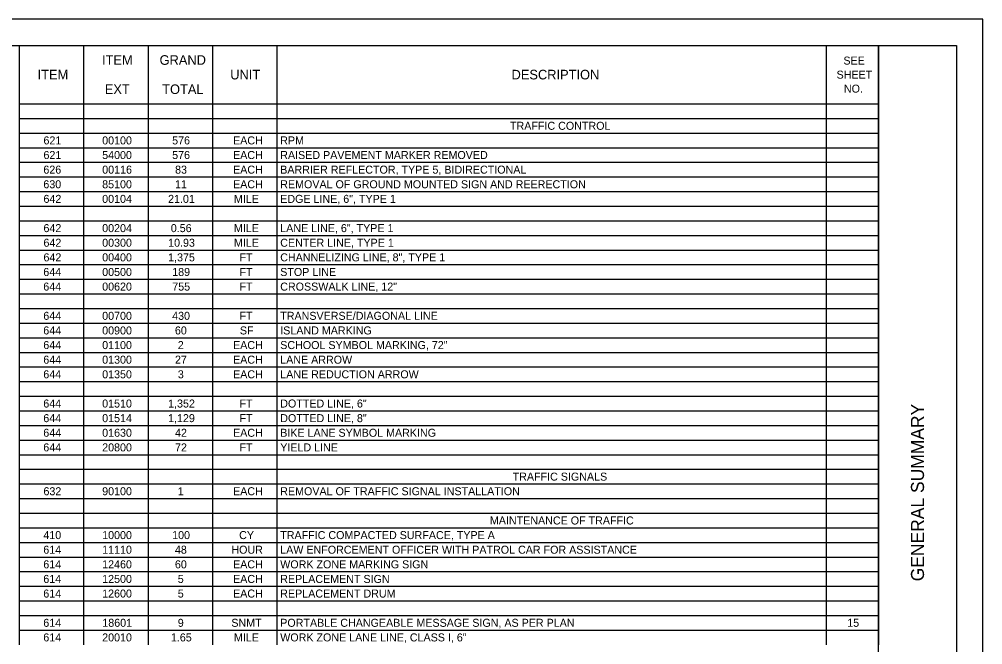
# Model space of a CAD drawing. Extents: x 0 to 34, y 0 to 22.
# Drawn here: x 15.54 to 34, y 10.02 to 22 of the extents above; entities that cross this region are included whole.
import ezdxf

# ---------------------------------------------------------------- set-up
doc = ezdxf.new("R2010")
doc.units = 0
for name, color, linetype in [('SH_Border', 7, 'Continuous'), ('SH_Cut_Line', 7, 'Continuous'), ('SH_Data', 7, 'Continuous'), ('SH_Text', 7, 'Continuous')]:
    doc.layers.add(name, color=color, linetype=linetype)

msp = doc.modelspace()

# ---------------------------------------------------------------- linework, layer by layer
at = {"layer": 'SH_Border'}
msp.add_line((32, 0.5), (32, 21.5), dxfattribs=at)
msp.add_lwpolyline([(1.5, 21.5), (33.5, 21.5), (33.5, 0.5), (1.5, 0.5)], close=True, dxfattribs=at)
at = {"layer": 'SH_Cut_Line'}
msp.add_lwpolyline([(0, 0), (34, 0), (34, 22), (0, 22)], close=True, dxfattribs=at)
at = {"layer": 'SH_Text'}
for p, q in [((15.537, 21.5), (18.005, 21.5)), ((15.537, 21.5), (15.537, 21.22)), ((16.771, 21.5), (16.771, 21.22)), ((18.005, 21.5), (19.239, 21.5)), ((18.005, 21.5), (18.005, 21.22)), ((19.239, 21.5), (32.004, 21.5)), ((19.239, 21.5), (19.239, 21.22)), ((20.473, 21.5), (20.473, 21.22)), ((31.001, 21.5), (31.001, 21.22)), ((32.004, 21.5), (32.004, 21.22)), ((15.537, 21.22), (15.537, 20.94)), ((16.771, 21.22), (16.771, 20.94)), ((18.005, 21.22), (18.005, 20.94)), ((19.239, 21.22), (19.239, 20.94)), ((20.473, 21.22), (20.473, 20.94)), ((31.001, 21.22), (31.001, 20.94)), ((32.004, 21.22), (32.004, 20.94)), ((15.537, 20.94), (15.537, 20.66)), ((16.771, 20.94), (16.771, 20.66)), ((18.005, 20.94), (18.005, 20.66)), ((19.239, 20.94), (19.239, 20.66)), ((20.473, 20.94), (20.473, 20.66)), ((31.001, 20.94), (31.001, 20.66)), ((32.004, 20.94), (32.004, 20.66)), ((15.537, 20.66), (15.537, 20.38)), ((16.771, 20.66), (16.771, 20.38)), ((18.005, 20.66), (18.005, 20.38)), ((19.239, 20.66), (19.239, 20.38)), ((20.473, 20.66), (20.473, 20.38)), ((31.001, 20.66), (31.001, 20.38)), ((32.004, 20.66), (32.004, 20.38)), ((15.537, 20.38), (18.005, 20.38)), ((15.537, 20.38), (15.537, 20.1)), ((16.771, 20.38), (16.771, 20.1)), ((18.005, 20.38), (19.239, 20.38)), ((18.005, 20.38), (18.005, 20.1)), ((19.239, 20.38), (32.004, 20.38)), ((19.239, 20.38), (19.239, 20.1)), ((20.473, 20.38), (20.473, 20.1)), ((31.001, 20.38), (31.001, 20.1)), ((32.004, 20.38), (32.004, 20.1)), ((15.537, 20.1), (18.005, 20.1)), ((15.537, 20.1), (15.537, 18.7)), ((16.771, 20.1), (16.771, 18.7)), ((18.005, 20.1), (19.239, 20.1)), ((18.005, 20.1), (18.005, 18.7)), ((19.239, 20.1), (32.004, 20.1)), ((19.239, 20.1), (19.239, 18.7)), ((20.473, 20.1), (20.473, 18.7)), ((31.001, 20.1), (31.001, 18.7)), ((32.004, 20.1), (32.004, 18.7)), ((15.537, 19.82), (18.005, 19.82)), ((18.005, 19.82), (19.239, 19.82)), ((19.239, 19.82), (32.004, 19.82)), ((15.537, 19.54), (18.005, 19.54)), ((18.005, 19.54), (19.239, 19.54)), ((19.239, 19.54), (32.004, 19.54)), ((15.537, 19.26), (18.005, 19.26)), ((18.005, 19.26), (19.239, 19.26)), ((19.239, 19.26), (32.004, 19.26)), ((15.537, 18.98), (18.005, 18.98)), ((18.005, 18.98), (19.239, 18.98)), ((19.239, 18.98), (32.004, 18.98)), ((15.537, 18.7), (18.005, 18.7)), ((15.537, 18.7), (15.537, 18.14)), ((16.771, 18.7), (16.771, 18.14)), ((18.005, 18.7), (19.239, 18.7)), ((18.005, 18.7), (18.005, 18.14)), ((19.239, 18.7), (32.004, 18.7)), ((19.239, 18.7), (19.239, 18.14)), ((20.473, 18.7), (20.473, 18.14)), ((31.001, 18.7), (31.001, 18.14)), ((32.004, 18.7), (32.004, 18.14)), ((15.537, 18.42), (18.005, 18.42)), ((18.005, 18.42), (19.239, 18.42)), ((19.239, 18.42), (32.004, 18.42)), ((15.537, 18.14), (18.005, 18.14)), ((15.537, 18.14), (15.537, 17.86)), ((16.771, 18.14), (16.771, 17.86)), ((18.005, 18.14), (19.239, 18.14)), ((18.005, 18.14), (18.005, 17.86)), ((19.239, 18.14), (32.004, 18.14)), ((19.239, 18.14), (19.239, 17.86)), ((20.473, 18.14), (20.473, 17.86)), ((31.001, 18.14), (31.001, 17.86)), ((32.004, 18.14), (32.004, 17.86)), ((15.537, 17.86), (18.005, 17.86)), ((15.537, 17.86), (15.537, 17.58)), ((16.771, 17.86), (16.771, 17.58)), ((18.005, 17.86), (19.239, 17.86)), ((18.005, 17.86), (18.005, 17.58)), ((19.239, 17.86), (32.004, 17.86)), ((19.239, 17.86), (19.239, 17.58)), ((20.473, 17.86), (20.473, 17.58)), ((31.001, 17.86), (31.001, 17.58)), ((32.004, 17.86), (32.004, 17.58)), ((15.537, 17.58), (18.005, 17.58)), ((15.537, 17.58), (15.537, 17.3)), ((16.771, 17.58), (16.771, 17.3)), ((18.005, 17.58), (19.239, 17.58)), ((18.005, 17.58), (18.005, 17.3)), ((19.239, 17.58), (32.004, 17.58)), ((19.239, 17.58), (19.239, 17.3)), ((20.473, 17.58), (20.473, 17.3)), ((31.001, 17.58), (31.001, 17.3)), ((32.004, 17.58), (32.004, 17.3)), ((15.537, 17.3), (18.005, 17.3)), ((15.537, 17.3), (15.537, 17.02)), ((16.771, 17.3), (16.771, 17.02)), ((18.005, 17.3), (19.239, 17.3)), ((18.005, 17.3), (18.005, 17.02)), ((19.239, 17.3), (32.004, 17.3)), ((19.239, 17.3), (19.239, 17.02)), ((20.473, 17.3), (20.473, 17.02)), ((31.001, 17.3), (31.001, 17.02)), ((32.004, 17.3), (32.004, 17.02)), ((15.537, 17.02), (18.005, 17.02)), ((15.537, 17.02), (15.537, 16.74)), ((16.771, 17.02), (16.771, 16.74)), ((18.005, 17.02), (19.239, 17.02)), ((18.005, 17.02), (18.005, 16.74)), ((19.239, 17.02), (32.004, 17.02)), ((19.239, 17.02), (19.239, 16.74)), ((20.473, 17.02), (20.473, 16.74)), ((31.001, 17.02), (31.001, 16.74)), ((32.004, 17.02), (32.004, 16.74)), ((15.537, 16.74), (18.005, 16.74)), ((15.537, 16.74), (15.537, 16.18)), ((16.771, 16.74), (16.771, 16.18)), ((18.005, 16.74), (19.239, 16.74)), ((18.005, 16.74), (18.005, 16.18)), ((19.239, 16.74), (32.004, 16.74)), ((19.239, 16.74), (19.239, 16.18)), ((20.473, 16.74), (20.473, 16.18)), ((31.001, 16.74), (31.001, 16.18)), ((32.004, 16.74), (32.004, 16.18)), ((15.537, 16.46), (18.005, 16.46)), ((18.005, 16.46), (19.239, 16.46)), ((19.239, 16.46), (32.004, 16.46)), ((15.537, 16.18), (18.005, 16.18)), ((15.537, 16.18), (15.537, 15.9)), ((16.771, 16.18), (16.771, 15.9)), ((18.005, 16.18), (19.239, 16.18)), ((18.005, 16.18), (18.005, 15.9)), ((19.239, 16.18), (32.004, 16.18)), ((19.239, 16.18), (19.239, 15.9)), ((20.473, 16.18), (20.473, 15.9)), ((31.001, 16.18), (31.001, 15.9)), ((32.004, 16.18), (32.004, 15.9)), ((15.537, 15.9), (18.005, 15.9)), ((15.537, 15.9), (15.537, 15.62)), ((16.771, 15.9), (16.771, 15.62)), ((18.005, 15.9), (19.239, 15.9)), ((18.005, 15.9), (18.005, 15.62)), ((19.239, 15.9), (32.004, 15.9)), ((19.239, 15.9), (19.239, 15.62)), ((20.473, 15.9), (20.473, 15.62)), ((31.001, 15.9), (31.001, 15.62)), ((32.004, 15.9), (32.004, 15.62)), ((15.537, 15.62), (18.005, 15.62)), ((15.537, 15.62), (15.537, 15.34)), ((16.771, 15.62), (16.771, 15.34)), ((18.005, 15.62), (19.239, 15.62)), ((18.005, 15.62), (18.005, 15.34)), ((19.239, 15.62), (32.004, 15.62)), ((19.239, 15.62), (19.239, 15.34)), ((20.473, 15.62), (20.473, 15.34)), ((31.001, 15.62), (31.001, 15.34)), ((32.004, 15.62), (32.004, 15.34)), ((15.537, 15.34), (18.005, 15.34)), ((15.537, 15.34), (15.537, 14.78)), ((16.771, 15.34), (16.771, 14.78)), ((18.005, 15.34), (19.239, 15.34)), ((18.005, 15.34), (18.005, 14.78)), ((19.239, 15.34), (32.004, 15.34)), ((19.239, 15.34), (19.239, 14.78)), ((20.473, 15.34), (20.473, 14.78)), ((31.001, 15.34), (31.001, 14.78)), ((32.004, 15.34), (32.004, 14.78)), ((15.537, 15.06), (18.005, 15.06)), ((18.005, 15.06), (19.239, 15.06)), ((19.239, 15.06), (32.004, 15.06)), ((15.537, 14.78), (18.005, 14.78)), ((15.537, 14.78), (15.537, 14.5)), ((16.771, 14.78), (16.771, 14.5)), ((18.005, 14.78), (19.239, 14.78)), ((18.005, 14.78), (18.005, 14.5)), ((19.239, 14.78), (32.004, 14.78)), ((19.239, 14.78), (19.239, 14.5)), ((20.473, 14.78), (20.473, 14.5)), ((31.001, 14.78), (31.001, 14.5)), ((32.004, 14.78), (32.004, 14.5)), ((15.537, 14.5), (18.005, 14.5)), ((15.537, 14.5), (15.537, 14.22)), ((16.771, 14.5), (16.771, 14.22)), ((18.005, 14.5), (19.239, 14.5)), ((18.005, 14.5), (18.005, 14.22)), ((19.239, 14.5), (32.004, 14.5)), ((19.239, 14.5), (19.239, 14.22)), ((20.473, 14.5), (20.473, 14.22)), ((31.001, 14.5), (31.001, 14.22)), ((32.004, 14.5), (32.004, 14.22)), ((15.537, 14.22), (18.005, 14.22)), ((15.537, 14.22), (15.537, 13.94)), ((16.771, 14.22), (16.771, 13.94)), ((18.005, 14.22), (19.239, 14.22)), ((18.005, 14.22), (18.005, 13.94)), ((19.239, 14.22), (32.004, 14.22)), ((19.239, 14.22), (19.239, 13.94)), ((20.473, 14.22), (20.473, 13.94)), ((31.001, 14.22), (31.001, 13.94)), ((32.004, 14.22), (32.004, 13.94)), ((15.537, 13.94), (18.005, 13.94)), ((15.537, 13.94), (15.537, 11.7)), ((16.771, 13.94), (16.771, 11.7)), ((18.005, 13.94), (19.239, 13.94)), ((18.005, 13.94), (18.005, 11.7)), ((19.239, 13.94), (32.004, 13.94)), ((19.239, 13.94), (19.239, 11.7)), ((20.473, 13.94), (20.473, 11.7)), ((31.001, 13.94), (31.001, 11.7)), ((32.004, 13.94), (32.004, 11.7)), ((15.537, 13.66), (18.005, 13.66)), ((18.005, 13.66), (19.239, 13.66)), ((19.239, 13.66), (32.004, 13.66)), ((15.537, 13.38), (18.005, 13.38)), ((18.005, 13.38), (19.239, 13.38)), ((19.239, 13.38), (32.004, 13.38)), ((15.537, 13.1), (18.005, 13.1)), ((18.005, 13.1), (19.239, 13.1)), ((19.239, 13.1), (32.004, 13.1)), ((15.537, 12.82), (18.005, 12.82)), ((18.005, 12.82), (19.239, 12.82)), ((19.239, 12.82), (32.004, 12.82)), ((15.537, 12.54), (18.005, 12.54)), ((18.005, 12.54), (19.239, 12.54)), ((19.239, 12.54), (32.004, 12.54)), ((15.537, 12.26), (18.005, 12.26)), ((18.005, 12.26), (19.239, 12.26)), ((19.239, 12.26), (32.004, 12.26)), ((15.537, 11.98), (18.005, 11.98)), ((18.005, 11.98), (19.239, 11.98)), ((19.239, 11.98), (32.004, 11.98)), ((15.537, 11.7), (18.005, 11.7)), ((15.537, 11.7), (15.537, 11.42)), ((16.771, 11.7), (16.771, 11.42)), ((18.005, 11.7), (19.239, 11.7)), ((18.005, 11.7), (18.005, 11.42)), ((19.239, 11.7), (32.004, 11.7)), ((19.239, 11.7), (19.239, 11.42)), ((20.473, 11.7), (20.473, 11.42)), ((31.001, 11.7), (31.001, 11.42)), ((32.004, 11.7), (32.004, 11.42)), ((15.537, 11.42), (18.005, 11.42)), ((15.537, 11.42), (15.537, 10.3)), ((16.771, 11.42), (16.771, 10.3)), ((18.005, 11.42), (19.239, 11.42)), ((18.005, 11.42), (18.005, 10.3)), ((19.239, 11.42), (32.004, 11.42)), ((19.239, 11.42), (19.239, 10.3)), ((20.473, 11.42), (20.473, 10.3)), ((31.001, 11.42), (31.001, 10.3)), ((32.004, 11.42), (32.004, 10.3)), ((15.537, 11.14), (18.005, 11.14)), ((18.005, 11.14), (19.239, 11.14)), ((19.239, 11.14), (32.004, 11.14)), ((15.537, 10.86), (18.005, 10.86)), ((18.005, 10.86), (19.239, 10.86)), ((19.239, 10.86), (32.004, 10.86)), ((15.537, 10.58), (18.005, 10.58)), ((18.005, 10.58), (19.239, 10.58)), ((19.239, 10.58), (32.004, 10.58)), ((15.537, 10.3), (18.005, 10.3)), ((15.537, 10.3), (15.537, 10.02)), ((16.771, 10.3), (16.771, 10.02)), ((18.005, 10.3), (19.239, 10.3)), ((18.005, 10.3), (18.005, 10.02)), ((19.239, 10.3), (32.004, 10.3)), ((19.239, 10.3), (19.239, 10.02)), ((20.473, 10.3), (20.473, 10.02)), ((31.001, 10.3), (31.001, 10.02)), ((32.004, 10.3), (32.004, 10.02))]:
    msp.add_line(p, q, dxfattribs=at)

# ---------------------------------------------------------------- texts
at = {"layer": 'SH_Data'}
msp.add_text('GENERAL SUMMARY', height=0.25, rotation=90, dxfattribs=at).set_placement((32.875, 11.235))
at = {"layer": 'SH_Text'}
for s, height, p in [('ITEM', 0.184, (17.123, 21.128)), ('GRAND', 0.184, (18.226, 21.128)), ('SEE ', 0.1533, (31.33, 21.132)), ('ITEM', 0.184, (15.889, 20.848)), ('UNIT', 0.184, (19.58, 20.848)), ('DESCRIPTION', 0.184, (24.971, 20.848)), ('SHEET ', 0.1533, (31.199, 20.863)), ('EXT', 0.184, (17.176, 20.568)), ('TOTAL', 0.184, (18.276, 20.568)), ('NO.', 0.1533, (31.34, 20.595)), ('TRAFFIC CONTROL', 0.15334, (24.941, 19.883)), ('621', 0.1533, (16.001, 19.603)), ('00100', 0.1533, (17.126, 19.603)), ('576', 0.1533, (18.467, 19.603)), ('EACH', 0.1533, (19.634, 19.603)), ('RPM', 0.1533, (20.538, 19.603)), ('621', 0.1533, (16.001, 19.323)), ('54000', 0.1533, (17.126, 19.323)), ('576', 0.1533, (18.467, 19.323)), ('EACH', 0.1533, (19.634, 19.323)), ('RAISED PAVEMENT MARKER REMOVED', 0.15334, (20.538, 19.323)), ('626', 0.1533, (15.999, 19.043)), ('00116', 0.1533, (17.127, 19.043)), ('83', 0.1533, (18.523, 19.043)), ('EACH', 0.1533, (19.634, 19.043)), ('BARRIER REFLECTOR, TYPE 5, BIDIRECTIONAL', 0.15334, (20.538, 19.043)), ('630', 0.1533, (15.999, 18.763)), ('85100', 0.1533, (17.126, 18.763)), ('11', 0.1533, (18.522, 18.763)), ('EACH', 0.1533, (19.634, 18.763)), ('REMOVAL OF GROUND MOUNTED SIGN AND REERECTION', 0.15334, (20.538, 18.763)), ('642', 0.1533, (16.001, 18.483)), ('00104', 0.1533, (17.126, 18.483)), ('21.01', 0.1533, (18.389, 18.483)), ('MILE', 0.1533, (19.651, 18.483)), ('EDGE LINE, 6", TYPE 1', 0.15334, (20.538, 18.483)), ('642', 0.1533, (16.001, 17.923)), ('00204', 0.1533, (17.126, 17.923)), ('0.56', 0.1533, (18.441, 17.923)), ('MILE', 0.1533, (19.651, 17.923)), ('LANE LINE, 6", TYPE 1', 0.15334, (20.538, 17.923)), ('642', 0.1533, (16.001, 17.643)), ('00300', 0.1533, (17.126, 17.643)), ('10.93', 0.1533, (18.39, 17.643)), ('MILE', 0.1533, (19.651, 17.643)), ('CENTER LINE, TYPE 1', 0.15334, (20.538, 17.643)), ('642', 0.1533, (16.001, 17.363)), ('00400', 0.1533, (17.126, 17.363)), ('1,375', 0.1533, (18.39, 17.363)), ('FT', 0.1533, (19.758, 17.363)), ('CHANNELIZING LINE, 8", TYPE 1', 0.15334, (20.538, 17.363)), ('644', 0.1533, (15.998, 17.083)), ('00500', 0.1533, (17.126, 17.083)), ('189', 0.1533, (18.468, 17.083)), ('FT', 0.1533, (19.758, 17.083)), ('STOP LINE', 0.1533, (20.538, 17.083)), ('644', 0.1533, (15.998, 16.803)), ('00620', 0.1533, (17.126, 16.803)), ('755', 0.1533, (18.469, 16.803)), ('FT', 0.1533, (19.758, 16.803)), ('CROSSWALK LINE, 12"', 0.15334, (20.538, 16.803)), ('644', 0.1533, (15.998, 16.243)), ('00700', 0.1533, (17.126, 16.243)), ('430', 0.1533, (18.467, 16.243)), ('FT', 0.1533, (19.758, 16.243)), ('TRANSVERSE/DIAGONAL LINE', 0.15334, (20.538, 16.243)), ('644', 0.1533, (15.998, 15.963)), ('00900', 0.1533, (17.126, 15.963)), ('60', 0.1533, (18.52, 15.963)), ('SF', 0.1533, (19.765, 15.963)), ('ISLAND MARKING', 0.15334, (20.538, 15.963)), ('644', 0.1533, (15.998, 15.683)), ('01100', 0.1533, (17.126, 15.683)), ('2', 0.153, (18.575, 15.683)), ('EACH', 0.1533, (19.634, 15.683)), ('SCHOOL SYMBOL MARKING, 72"', 0.15334, (20.538, 15.683)), ('644', 0.1533, (15.998, 15.403)), ('01300', 0.1533, (17.126, 15.403)), ('27', 0.1533, (18.521, 15.403)), ('EACH', 0.1533, (19.634, 15.403)), ('LANE ARROW', 0.1533, (20.538, 15.403)), ('644', 0.1533, (15.998, 15.123)), ('01350', 0.1533, (17.126, 15.123)), ('3', 0.153, (18.576, 15.123)), ('EACH', 0.1533, (19.634, 15.123)), ('LANE REDUCTION ARROW', 0.15334, (20.538, 15.123)), ('644', 0.1533, (15.998, 14.563)), ('01510', 0.1533, (17.126, 14.563)), ('1,352', 0.1533, (18.39, 14.563)), ('FT', 0.1533, (19.758, 14.563)), ('DOTTED LINE, 6"', 0.15334, (20.538, 14.563)), ('644', 0.1533, (15.998, 14.283)), ('01514', 0.1533, (17.126, 14.283)), ('1,129', 0.1533, (18.389, 14.283)), ('FT', 0.1533, (19.758, 14.283)), ('DOTTED LINE, 8"', 0.15334, (20.538, 14.283)), ('644', 0.1533, (15.998, 14.003)), ('01630', 0.1533, (17.126, 14.003)), ('42', 0.1533, (18.522, 14.003)), ('EACH', 0.1533, (19.634, 14.003)), ('BIKE LANE SYMBOL MARKING', 0.15334, (20.538, 14.003)), ('644', 0.1533, (15.998, 13.723)), ('20800', 0.1533, (17.126, 13.723)), ('72', 0.1533, (18.522, 13.723)), ('FT', 0.1533, (19.758, 13.723)), ('YIELD LINE', 0.1533, (20.538, 13.723)), ('TRAFFIC SIGNALS', 0.15334, (24.992, 13.163)), ('632', 0.1533, (16.001, 12.883)), ('90100', 0.1533, (17.126, 12.883)), ('1', 0.153, (18.575, 12.883)), ('EACH', 0.1533, (19.634, 12.883)), ('REMOVAL OF TRAFFIC SIGNAL INSTALLATION', 0.15334, (20.538, 12.883)), ('MAINTENANCE OF TRAFFIC', 0.15334, (24.556, 12.323)), ('410', 0.1533, (15.999, 12.043)), ('10000', 0.1533, (17.126, 12.043)), ('100', 0.1533, (18.467, 12.043)), ('CY', 0.1533, (19.751, 12.043)), ('TRAFFIC COMPACTED SURFACE, TYPE A', 0.15334, (20.538, 12.043)), ('614', 0.1533, (15.998, 11.763)), ('11110', 0.1533, (17.126, 11.763)), ('48', 0.1533, (18.52, 11.763)), ('HOUR', 0.1533, (19.602, 11.763)), ('LAW ENFORCEMENT OFFICER WITH PATROL CAR FOR ASSISTANCE', 0.15334, (20.538, 11.763)), ('614', 0.1533, (15.998, 11.483)), ('12460', 0.1533, (17.126, 11.483)), ('60', 0.1533, (18.52, 11.483)), ('EACH', 0.1533, (19.634, 11.483)), ('WORK ZONE MARKING SIGN', 0.15334, (20.538, 11.483)), ('614', 0.1533, (15.998, 11.203)), ('12500', 0.1533, (17.126, 11.203)), ('5', 0.153, (18.575, 11.203)), ('EACH', 0.1533, (19.634, 11.203)), ('REPLACEMENT SIGN', 0.15334, (20.538, 11.203)), ('614', 0.1533, (15.998, 10.923)), ('12600', 0.1533, (17.126, 10.923)), ('EACH', 0.1533, (19.634, 10.923)), ('REPLACEMENT DRUM', 0.15334, (20.538, 10.923)), ('5', 0.153, (18.575, 10.923)), ('614', 0.1533, (15.998, 10.363)), ('18601', 0.1533, (17.129, 10.363)), ('9', 0.153, (18.575, 10.363)), ('SNMT', 0.1533, (19.601, 10.363)), ('PORTABLE CHANGEABLE MESSAGE SIGN, AS PER PLAN', 0.15334, (20.538, 10.363)), ('15', 0.1533, (31.403, 10.363)), ('614', 0.1533, (15.998, 10.083)), ('20010', 0.1533, (17.126, 10.083)), ('1.65', 0.1533, (18.443, 10.083)), ('MILE', 0.1533, (19.651, 10.083)), ('WORK ZONE LANE LINE, CLASS I, 6"', 0.15334, (20.538, 10.083))]:
    msp.add_text(s, height=height, dxfattribs=at).set_placement(p)

doc.saveas('drawing.dxf')
